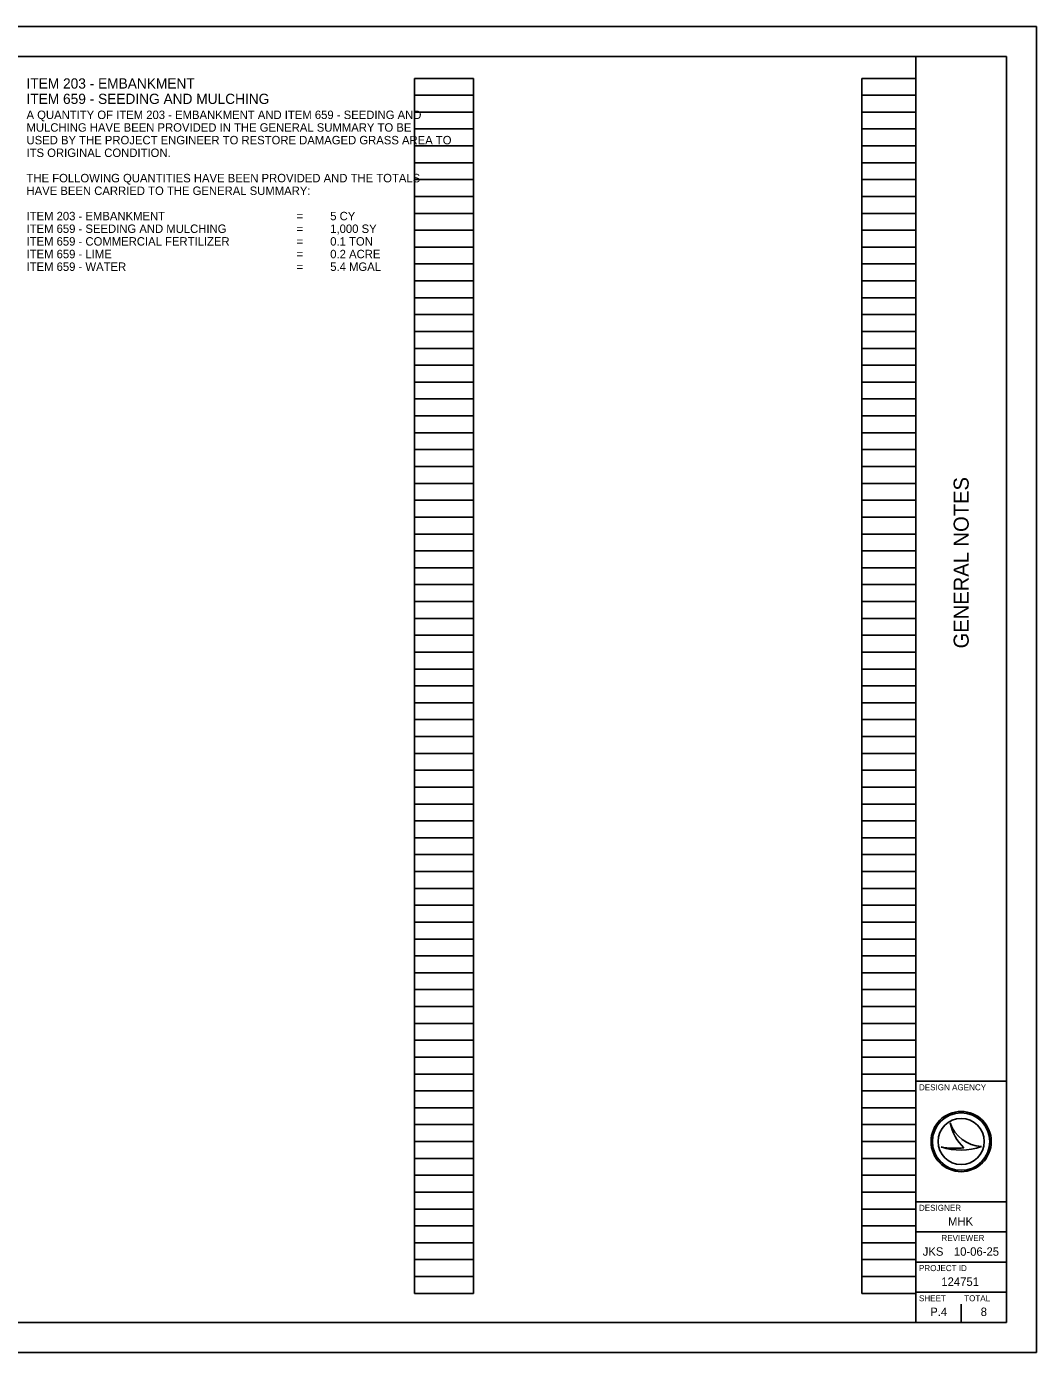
# Model space of a CAD drawing. Extents: x 0 to 34, y 0 to 22.
# Drawn here: x 17.24 to 34, y 0 to 22 of the extents above; entities that cross this region are included whole.
import ezdxf

# ---------------------------------------------------------------- set-up
doc = ezdxf.new("R2010")
doc.units = 0
for name, color, linetype in [('SH_Border', 7, 'Continuous'), ('SH_Cut_Line', 7, 'Continuous'), ('SH_Data', 7, 'Continuous'), ('SH_Text', 7, 'Continuous')]:
    doc.layers.add(name, color=color, linetype=linetype)

msp = doc.modelspace()

# ---------------------------------------------------------------- linework, layer by layer
at = {"layer": 'SH_Border'}
for p, q in [((32, 0.5), (32, 21.5)), ((32, 4.5), (33.5, 4.5)), ((32, 2.5), (33.5, 2.5)), ((32, 2), (33.5, 2)), ((32, 1.5), (33.5, 1.5)), ((32, 1), (33.5, 1))]:
    msp.add_line(p, q, dxfattribs=at)
msp.add_lwpolyline([(1.5, 21.5), (33.5, 21.5), (33.5, 0.5), (1.5, 0.5)], close=True, dxfattribs=at)
at = {"layer": 'SH_Cut_Line'}
msp.add_lwpolyline([(0, 0), (34, 0), (34, 22), (0, 22)], close=True, dxfattribs=at)
at = {"layer": 'SH_Data'}
for p, q in [((23.68, 0.98), (23.68, 21.14)), ((23.68, 21.14), (24.66, 21.14)), ((24.66, 0.98), (24.66, 21.14)), ((31.1, 0.98), (31.1, 21.14)), ((31.1, 21.14), (32, 21.14)), ((32, 0.98), (32, 21.14)), ((23.68, 20.86), (24.66, 20.86)), ((31.1, 20.86), (32, 20.86)), ((23.68, 20.58), (24.66, 20.58)), ((31.1, 20.58), (32, 20.58)), ((23.68, 20.3), (24.66, 20.3)), ((31.1, 20.3), (32, 20.3)), ((23.68, 20.02), (24.66, 20.02)), ((31.1, 20.02), (32, 20.02)), ((23.68, 19.74), (24.66, 19.74)), ((31.1, 19.74), (32, 19.74)), ((23.68, 19.46), (24.66, 19.46)), ((31.1, 19.46), (32, 19.46)), ((23.68, 19.18), (24.66, 19.18)), ((31.1, 19.18), (32, 19.18)), ((23.68, 18.9), (24.66, 18.9)), ((31.1, 18.9), (32, 18.9)), ((23.68, 18.62), (24.66, 18.62)), ((31.1, 18.62), (32, 18.62)), ((23.68, 18.34), (24.66, 18.34)), ((31.1, 18.34), (32, 18.34)), ((23.68, 18.06), (24.66, 18.06)), ((31.1, 18.06), (32, 18.06)), ((23.68, 17.78), (24.66, 17.78)), ((31.1, 17.78), (32, 17.78)), ((23.68, 17.5), (24.66, 17.5)), ((31.1, 17.5), (32, 17.5)), ((23.68, 17.22), (24.66, 17.22)), ((31.1, 17.22), (32, 17.22)), ((23.68, 16.94), (24.66, 16.94)), ((31.1, 16.94), (32, 16.94)), ((23.68, 16.66), (24.66, 16.66)), ((31.1, 16.66), (32, 16.66)), ((23.68, 16.38), (24.66, 16.38)), ((31.1, 16.38), (32, 16.38)), ((23.68, 16.1), (24.66, 16.1)), ((31.1, 16.1), (32, 16.1)), ((23.68, 15.82), (24.66, 15.82)), ((31.1, 15.82), (32, 15.82)), ((23.68, 15.54), (24.66, 15.54)), ((31.1, 15.54), (32, 15.54)), ((23.68, 15.26), (24.66, 15.26)), ((31.1, 15.26), (32, 15.26)), ((23.68, 14.98), (24.66, 14.98)), ((31.1, 14.98), (32, 14.98)), ((23.68, 14.7), (24.66, 14.7)), ((31.1, 14.7), (32, 14.7)), ((23.68, 14.42), (24.66, 14.42)), ((31.1, 14.42), (32, 14.42)), ((23.68, 14.14), (24.66, 14.14)), ((31.1, 14.14), (32, 14.14)), ((23.68, 13.86), (24.66, 13.86)), ((31.1, 13.86), (32, 13.86)), ((23.68, 13.58), (24.66, 13.58)), ((31.1, 13.58), (32, 13.58)), ((23.68, 13.3), (24.66, 13.3)), ((31.1, 13.3), (32, 13.3)), ((23.68, 13.02), (24.66, 13.02)), ((31.1, 13.02), (32, 13.02)), ((23.68, 12.74), (24.66, 12.74)), ((31.1, 12.74), (32, 12.74)), ((23.68, 12.46), (24.66, 12.46)), ((31.1, 12.46), (32, 12.46)), ((23.68, 12.18), (24.66, 12.18)), ((31.1, 12.18), (32, 12.18)), ((23.68, 11.9), (24.66, 11.9)), ((31.1, 11.9), (32, 11.9)), ((23.68, 11.62), (24.66, 11.62)), ((31.1, 11.62), (32, 11.62)), ((23.68, 11.34), (24.66, 11.34)), ((31.1, 11.34), (32, 11.34)), ((23.68, 11.06), (24.66, 11.06)), ((31.1, 11.06), (32, 11.06)), ((23.68, 10.78), (24.66, 10.78)), ((31.1, 10.78), (32, 10.78)), ((23.68, 10.5), (24.66, 10.5)), ((31.1, 10.5), (32, 10.5)), ((23.68, 10.22), (24.66, 10.22)), ((31.1, 10.22), (32, 10.22)), ((23.68, 9.94), (24.66, 9.94)), ((31.1, 9.94), (32, 9.94)), ((23.68, 9.66), (24.66, 9.66)), ((31.1, 9.66), (32, 9.66)), ((23.68, 9.38), (24.66, 9.38)), ((31.1, 9.38), (32, 9.38)), ((23.68, 9.1), (24.66, 9.1)), ((31.1, 9.1), (32, 9.1)), ((23.68, 8.82), (24.66, 8.82)), ((31.1, 8.82), (32, 8.82)), ((23.68, 8.54), (24.66, 8.54)), ((31.1, 8.54), (32, 8.54)), ((23.68, 8.26), (24.66, 8.26)), ((31.1, 8.26), (32, 8.26)), ((23.68, 7.98), (24.66, 7.98)), ((31.1, 7.98), (32, 7.98)), ((23.68, 7.7), (24.66, 7.7)), ((31.1, 7.7), (32, 7.7)), ((23.68, 7.42), (24.66, 7.42)), ((31.1, 7.42), (32, 7.42)), ((23.68, 7.14), (24.66, 7.14)), ((31.1, 7.14), (32, 7.14)), ((23.68, 6.86), (24.66, 6.86)), ((31.1, 6.86), (32, 6.86)), ((23.68, 6.58), (24.66, 6.58)), ((31.1, 6.58), (32, 6.58)), ((23.68, 6.3), (24.66, 6.3)), ((31.1, 6.3), (32, 6.3)), ((23.68, 6.02), (24.66, 6.02)), ((31.1, 6.02), (32, 6.02)), ((23.68, 5.74), (24.66, 5.74)), ((31.1, 5.74), (32, 5.74)), ((23.68, 5.46), (24.66, 5.46)), ((31.1, 5.46), (32, 5.46)), ((23.68, 5.18), (24.66, 5.18)), ((31.1, 5.18), (32, 5.18)), ((23.68, 4.9), (24.66, 4.9)), ((31.1, 4.9), (32, 4.9)), ((23.68, 4.62), (24.66, 4.62)), ((31.1, 4.62), (32, 4.62)), ((23.68, 4.34), (24.66, 4.34)), ((31.1, 4.34), (32, 4.34)), ((23.68, 4.06), (24.66, 4.06)), ((31.1, 4.06), (32, 4.06)), ((23.68, 3.78), (24.66, 3.78)), ((31.1, 3.78), (32, 3.78)), ((32.567, 3.81), (32.567, 3.81)), ((23.68, 3.5), (24.66, 3.5)), ((31.1, 3.5), (32, 3.5)), ((32.417, 3.41), (32.417, 3.41)), ((32.75, 3.5), (32.75, 3.5)), ((33.087, 3.419), (33.087, 3.419)), ((23.68, 3.22), (24.66, 3.22)), ((31.1, 3.22), (32, 3.22)), ((23.68, 2.94), (24.66, 2.94)), ((31.1, 2.94), (32, 2.94)), ((23.68, 2.66), (24.66, 2.66)), ((31.1, 2.66), (32, 2.66)), ((23.68, 2.38), (24.66, 2.38)), ((31.1, 2.38), (32, 2.38)), ((23.68, 2.1), (24.66, 2.1)), ((31.1, 2.1), (32, 2.1)), ((23.68, 1.82), (24.66, 1.82)), ((31.1, 1.82), (32, 1.82)), ((23.68, 1.54), (24.66, 1.54)), ((31.1, 1.54), (32, 1.54)), ((23.68, 1.26), (24.66, 1.26)), ((31.1, 1.26), (32, 1.26)), ((23.68, 0.98), (24.66, 0.98)), ((31.1, 0.98), (32, 0.98)), ((32.375, 0.675), (32.375, 0.675)), ((32.75, 0.5), (32.75, 0.8))]:
    msp.add_line(p, q, dxfattribs=at)
for radius in [0.5, 0.477, 0.477, 0.382]:
    msp.add_circle((32.75, 3.5), radius, dxfattribs=at)
for centre, radius, start, end in [((33.116, 3.998), 0.58, 198.9257, 198.9319), ((33.347, 3.97), 0.796, 191.6379, 191.6421), ((33.116, 3.998), 0.58, 198.9319, 267.1657), ((33.347, 3.97), 0.796, 191.6421, 226.0947), ((32.739, 4.37), 1.013, 251.4576, 290.0832), ((32.648, 4.654), 1.266, 259.4964, 259.4995), ((32.739, 4.37), 1.013, 251.4527, 251.4576), ((32.648, 4.654), 1.266, 259.4995, 276.6672)]:
    msp.add_arc(centre, radius, start, end, dxfattribs=at)

# ---------------------------------------------------------------- texts
msp.add_text('GENERAL NOTES', height=0.25, rotation=90, dxfattribs=at).set_placement((32.875, 11.682))
for s, height, p in [('DESIGN AGENCY', 0.1, (32.05, 4.35)), ('DESIGNER', 0.1, (32.05, 2.35)), ('MHK', 0.14, (32.532, 2.105)), ('REVIEWER', 0.1, (32.422, 1.85)), ('JKS', 0.14, (32.112, 1.605)), ('10-06-25', 0.14, (32.629, 1.605)), ('PROJECT ID', 0.1, (32.05, 1.35)), ('124751', 0.14, (32.421, 1.105)), ('SHEET', 0.1, (32.05, 0.85)), ('TOTAL', 0.1, (32.8, 0.85)), ('P.4', 0.14, (32.237, 0.605)), ('8', 0.14, (33.074, 0.605))]:
    msp.add_text(s, height=height, dxfattribs=at).set_placement(p)
at = {"layer": 'SH_Text'}
for s, height, p in [('ITEM 203 - EMBANKMENT', 0.17, (17.24, 20.97)), ('ITEM 659 - SEEDING AND MULCHING', 0.17, (17.24, 20.715)), ('A QUANTITY OF ITEM 203 - EMBANKMENT AND ITEM 659 - SEEDING AND ', 0.14, (17.24, 20.465)), ('MULCHING HAVE BEEN PROVIDED IN THE GENERAL SUMMARY TO BE ', 0.14, (17.24, 20.255)), ('USED BY THE PROJECT ENGINEER TO RESTORE DAMAGED GRASS AREA TO ', 0.14, (17.24, 20.045)), ('ITS ORIGINAL CONDITION.', 0.14, (17.24, 19.835)), ('THE FOLLOWING QUANTITIES HAVE BEEN PROVIDED AND THE TOTALS ', 0.14, (17.24, 19.415)), ('HAVE BEEN CARRIED TO THE GENERAL SUMMARY:', 0.14, (17.24, 19.205)), ('ITEM 203 - EMBANKMENT', 0.14, (17.24, 18.785)), ('5 CY', 0.14, (22.28, 18.785)), ('ITEM 659 - SEEDING AND MULCHING', 0.14, (17.24, 18.575)), ('=', 0.14, (21.72, 18.785)), ('1,000 SY', 0.14, (22.28, 18.575)), ('ITEM 659 - COMMERCIAL FERTILIZER', 0.14, (17.24, 18.365)), ('=', 0.14, (21.72, 18.575)), ('0.1 TON', 0.14, (22.28, 18.365)), ('ITEM 659 - LIME', 0.14, (17.24, 18.155)), ('=', 0.14, (21.72, 18.365)), ('0.2 ACRE', 0.14, (22.28, 18.155)), ('ITEM 659 - WATER', 0.14, (17.24, 17.945)), ('=', 0.14, (21.72, 18.155)), ('=', 0.14, (21.72, 17.945)), ('5.4 MGAL', 0.14, (22.28, 17.945))]:
    msp.add_text(s, height=height, dxfattribs=at).set_placement(p)

doc.saveas('drawing.dxf')
